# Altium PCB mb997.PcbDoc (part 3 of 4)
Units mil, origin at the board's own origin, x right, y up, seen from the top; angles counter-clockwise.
Board outline 2598.43 x 3818.9 mil, 2 copper layers (Top, Bottom), stack 62.402 mil thick; 205 components, 190 nets, 761 pads, 492 vias.
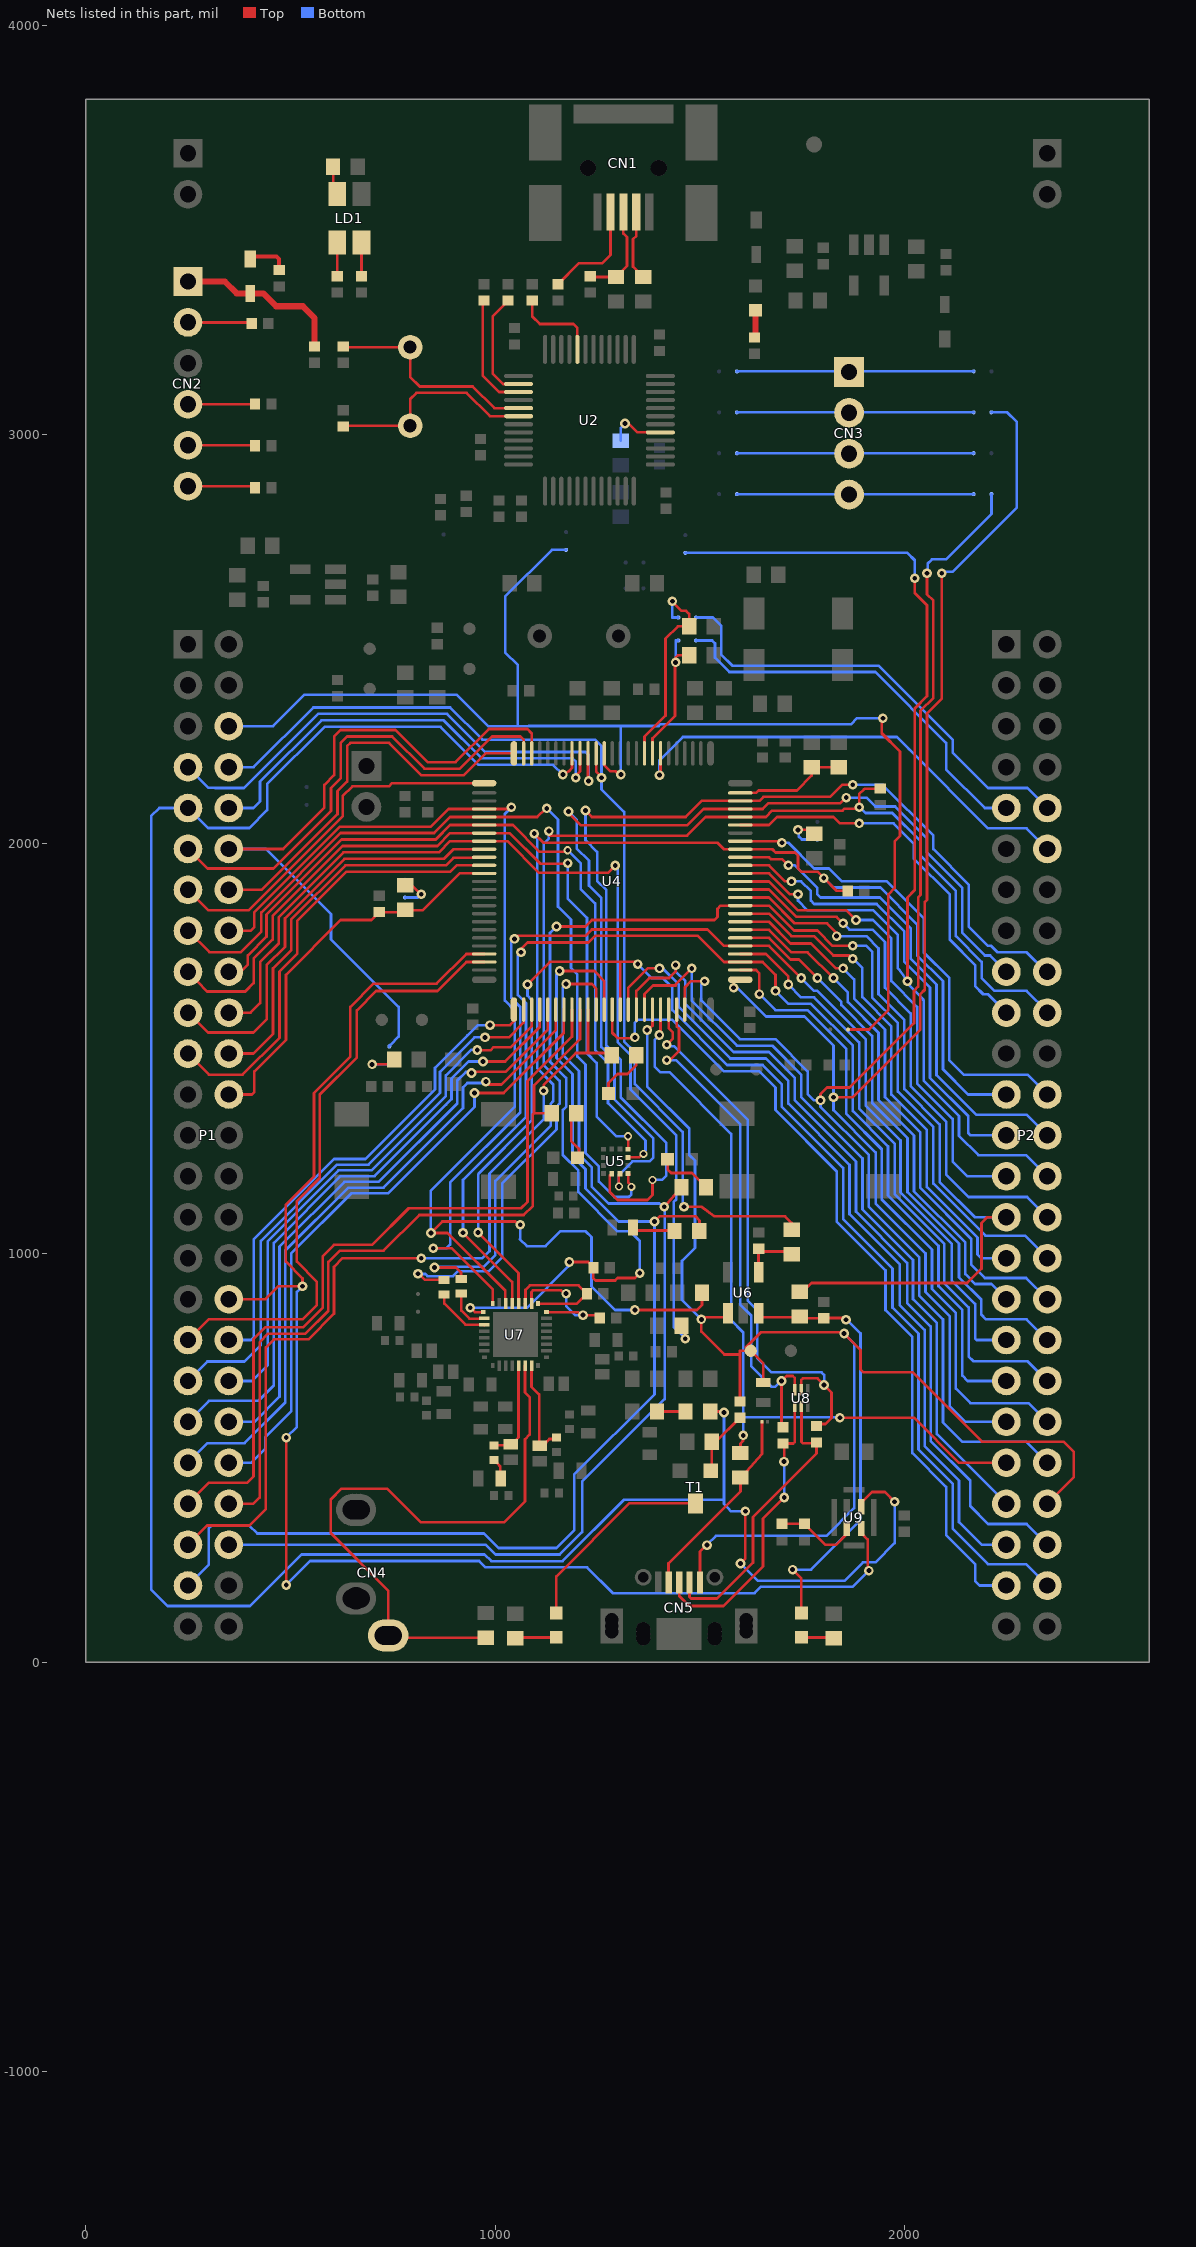
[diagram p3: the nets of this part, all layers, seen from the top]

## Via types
v1: diameter 23.62, hole 11.81, Top to Bottom, 485 vias
v2: diameter 19.68, hole 11.81, Top to Bottom, 7 vias

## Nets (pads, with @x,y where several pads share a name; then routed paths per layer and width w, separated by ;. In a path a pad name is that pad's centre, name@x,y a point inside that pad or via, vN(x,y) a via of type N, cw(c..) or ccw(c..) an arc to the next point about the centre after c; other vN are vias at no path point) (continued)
NetC63_2: C63.2 L6.1 U7.15 | length 254.3
  Top w6.5: U7.15@1088.58,724.59 1088.58,673.06 1107.37,654.27 1107.37,537.14 1105.54,535.31 L6.1@1097.6,535.31 ; L6.1@1110.24,527.6 1115.16,527.6 1124.7,537.14 1124.7,538.11 1132.25,545.66 1145.6,545.66 C63.2@1149.21,549.27
NetC64_1: C64.1 R70.2 | length 51.2
  Top w6.5: C64.1@997.24,493.68 998.23,493.68 1005.02,486.89 1005.02,485.91 1012.32,478.61 1012.32,459.62 R70.2@1019.63,452.3
NetC64_2: C64.2 L7.1 U7.13 | length 243.6
  Top w6.5: C64.2@997.24,529.11 998.23,530.1 1038.03,530.1 1057.09,549.15 U7.13@1057.09,724.59
NetCN1_2: CN1.2 R11.1 | length 171.9
  Top w6.5: CN1.2@1344.73,3543.35 1344.73,3485.44 1336.86,3477.57 1336.86,3410.46 R11.1@1362.17,3385.16
NetCN1_3: CN1.3 R9.1 R10.1 | length 236.6
  Top w6.5: R9.1@1232.24,3386.97 1234.06,3385.16 R10.1@1295.24,3385.16 1295.24,3385.32 1321.94,3412.02 1321.94,3482.43 1313.23,3491.14 CN1.3@1313.23,3543.35
NetCN1_4: CN1.4 R8.1 | length 262.3
  Top w6.5: R8.1@1153.5,3367.28 1205.12,3418.9 1261.73,3418.9 1281.73,3438.9 CN1.4@1281.73,3543.35
NetCN2_1: CN2.1 D2.1 R13.1 | length 415.4
  Top w15: CN2.1@249.21,3374.02 339.2,3374.02 368.33,3344.88 D2.1@401.57,3344.88 433.07,3344.88 464.57,3313.39 529.92,3313.39 558.21,3285.09 R13.1@558.21,3215.5
NetCN2_2: CN2.2 R12.1 | length 157
  Top w6.5: CN2.2@249.21,3274.02 402.83,3274.02 R12.1@405.2,3271.65
NetCN2_4: CN2.4 R15.1 | length 164.2
  Top w6.5: CN2.4@249.21,3074.02 412.28,3074.02 R15.1@413.07,3074.8
NetCN2_5: CN2.5 R16.1 | length 164.5
  Top w6.5: CN2.5@249.21,2974.02 411.5,2974.02 R16.1@413.07,2972.44
NetCN2_6: CN2.6 R17.1 | length 167.8
  Top w6.5: CN2.6@249.21,2874.02 413.07,2874.02 R17.1@413.07,2870.08
NetCN3_1: CN3.1 SB2.1 SB3.2 | length 578.7
  Bottom w6.5: SB2.1@1590.51,3154.37 1862.17,3154.37 SB3.2@2169.25,3154.37
NetCN3_2: CN3.2 SB4.1 SB5.2 | length 578.7
  Bottom w6.5: SB4.1@1590.51,3054.37 1862.17,3054.37 SB5.2@2169.25,3054.37
NetCN3_3: CN3.3 SB6.1 SB7.2 | length 578.7
  Bottom w6.5: SB6.1@1590.51,2954.37 1862.17,2954.37 SB7.2@2169.25,2954.37
NetCN3_4: CN3.4 SB8.1 SB9.2 | length 578.7
  Bottom w6.5: SB8.1@1590.51,2854.37 1862.17,2854.37 SB9.2@2169.25,2854.37
NetCN4_1: CN4.1 R65.1 U7.14 | length 1505.4
  Top w6.5: CN4.1@738.58,65.36 738.58,174.83 598.14,315.27 598.14,398.07 624.25,424.18 736.02,424.18 818.21,342 1021.94,342 1072.71,392.77 1072.71,544.84 1084.24,556.36 1084.24,647.68 1072.71,659.2 U7.14@1072.71,724.47 ; CN4.1@743.78,60.16 R65.1@976.54,60.16
NetCN5_2: CN5.2 R58.2 U8.2 | length 711.6
  Top w6.5: CN5.2@1474.8,194.9 1474.8,159.44 1478.61,155.64 1541.99,155.64 1629.75,243.4 1629.75,354.8 1785.15,510.19 1785.15,529.97 R58.2@1780.32,534.8 ; U8.2@1747.77,624.84 1748.46,624.16 1748.46,538.61 1752.26,534.8 1777.75,534.8 1782.56,534.8 R58.2@1784.91,537.15
NetCN5_3: CN5.3 R60.2 U8.1 | length 733
  Top w6.5: CN5.3@1449.21,194.9 1449.74,194.37 1449.74,162.38 1474.8,137.32 1557.71,137.32 1654.2,233.81 1654.2,350.71 v1(1706.23,402.74) ; R60.2@1703.33,534.49 1705.88,531.93 v1(1705.88,490.3) ; R60.2@1705.88,534.65 1728.21,534.65 1732.02,538.46 U8.1@1732.02,632.74
  Bottom w6.5: v1(1705.88,490.3) 1706.06,490.12 1706.06,402.91 v1(1706.23,402.74)
NetCN5_4: CN5.4 R59.1 U11.1 | length 485.7
  Top w6.5: CN5.4@1423.62,194.9 1423.62,241.67 1599.21,417.26 R59.1@1599.21,451.4 1614.13,465.65 1651.86,509.22 U11.1@1651.86,587.4
NetD2_2: D2.2 R2.1 | length 112.4
  Top w10: D2.2@401.57,3429.13 401.57,3434.9 465.21,3434.9 471.21,3428.9 471.21,3405.51 R2.1@468.82,3405.51 ; R2.1@465.21,3405.51 R2.1@468.82,3405.51 ; R2.1@472.44,3401.89 R2.1@468.82,3405.51
NetLD1_2: LD1.2 R4.2 | length 82.4
  Top w6.5: R4.2@673.19,3386.97 LD1.2@673.19,3469.33
NetLD1_3: LD1.3 R3.2 | length 82.4
  Top w6.5: R3.2@614.13,3386.97 LD1.3@614.13,3469.33
NetLD1_4: LD1.4 R1.1 | length 91.2
  Top w6.5: R1.1@603.82,3654.37 603.82,3587.28 607.09,3590.55 612.15,3595.61 613.82,3583.82 LD1.4@614.13,3583.5
NetLD2_1: LD2.1 R14.1 | length 66.8
  Top w13.78: R14.1@1633.82,3237.36 1636.12,3239.67 LD2.1@1636.12,3303.17
NetLD3_1: LD3.1 R36.1 | length 135.4
  Top w6.5: LD3.1@1276.93,1389.76 1276.93,1415.12 1299.21,1437.41 1322.82,1437.41 1344.95,1459.54 R36.1@1344.95,1483.15
NetLD4_1: LD4.1 R40.1 | length 123.4
  Top w6.5: R40.1@1198.04,1341.61 1185.55,1329.11 1185.55,1273.73 1204.72,1254.55 1204.72,1236.67 LD4.1@1200.95,1232.9
NetLD5_1: LD5.1 R41.1 | length 136.6
  Top w6.5: LD5.1@1421.3,1229.04 1421.3,1204.28 1430.18,1195.4 1480.71,1195.4 R41.1@1515.21,1160.9
NetLD6_1: LD6.1 R42.1 | length 105
  Top w6.5: LD6.1@1336.85,1062.75 1344.39,1055.21 1436.9,1055.21 R42.1@1438.21,1053.9
NetLD7_1: LD7.1 R66.1 | length 100.7
  Top w6.5: R66.1@1049.21,58.9 1050.87,60.55 LD7.1@1149.21,60.55
NetLD7_2: LD7.2 T1.3 | length 503.9
  Top w6.5: LD7.2@1149.21,120.55 1149.21,209.9 1328.21,388.9 1488.21,388.9 T1.3@1489.21,387.9
NetLD8_1: LD8.1 R67.1 | length 80.3
  Top w6.5: LD8.1@1748.03,60.55 1825.98,60.55 R67.1@1827.64,58.9
NetLD8_2: LD8.2 R50.2 R51.2 U6.3 | length 1047.2
  Top w6.5: U6.3@1643.54,842.9 1733.26,842.9 R50.2@1735.98,840.18 ; v1(1726.71,226.4) 1748.03,205.08 LD8.2@1748.03,120.55 ; R50.2@1743.81,845.06 1748.21,840.66 R51.2@1802.76,840.62 ; R51.2@1802.76,840.62 1803.27,841.13 1848.35,841.13 1852.58,836.9 v1(1857.21,836.9)
  Bottom w6.5: v1(1726.71,226.4) 1771.71,226.4 1892.75,347.44 1892.75,803.9 1859.75,836.9 v1(1857.21,836.9)
NetR5_2: R5.2 U2.3 | length 289.2
  Top w6.5: R5.2@972.4,3327.28 972.4,3318.9 969.21,3315.71 969.21,3143.9 1009.21,3103.9 U2.3@1057.11,3103.9
NetR6_2: R6.2 U2.2 | length 267.6
  Top w6.5: R6.2@1031.46,3327.28 1031.46,3326.46 993.9,3288.9 993.9,3148.9 1019.21,3123.58 U2.2@1057.11,3123.58
NetR7_2: R7.2 U2.44 | length 212.5
  Top w6.5: R7.2@1090.51,3327.28 1090.51,3288.9 1109.21,3270.2 1190.81,3270.2 1200.81,3260.2 U2.44@1200.81,3208.23
NetR27_1: R27.1 R28.1 U4.99 | length 278.2
  Top w6.5: U4.99@1598.96,2124.48 1637.62,2124.48 1643.45,2130.31 1737.21,2130.31 1773.21,2166.31 R27.1@1773.21,2186.9 R28.1@1839.21,2186.9
NetR30_1: R30.1 SB18.2 | length 110.5
  Top w6.5: v1(1739.93,2034.05) 1771.41,2034.05 1771.41,2032.57 R30.1@1779.28,2024.7
  Bottom w6.5: v1(1739.93,2034.05) 1741.71,2034.04 1741.71,2017.93 1749.21,2010.43 SB18.2@1787.15,2010.43
NetR32_2: R32.2 SB19.2 | length 91.7
  Top w6.5: R32.2@779.79,1898.78 R32.2@780.5,1899.43 ; R32.2@780.53,1899.46 795.53,1899.46 818.35,1876.65 v1(819.14,1876.65)
  Bottom w6.5: SB19.2@779.79,1868.77 v1@811.27,1868.77 ; v1@811.27,1868.78 v1(819.14,1876.65)
NetR35_1: R35.1 SB20.2 | length 114.6
  Top w6.5: v1(699.21,1460.9) 744.83,1460.9 759.21,1475.28 R35.1@753.21,1472.9
  Bottom w6.5: v1(699.21,1460.9) 740.83,1460.9 SB20.2@741.21,1461.28
NetR45_2: R45.2 R46.1 U6.4 | length 134.5
  Top w6.5: U6.4@1643.54,942.9 R45.2@1643.54,1000.99 ; R45.2@1650.69,1003.76 1717.12,1003.76 R46.1@1724.19,996.69
NetR47_2: R47.2 U7.25 U7.27 | length 328.2
  Top w6.5: U7.27@1072.83,876.13 1073.92,877.22 1073.92,910.15 1084.71,920.95 1203.94,920.95 1213.59,911.3 1214.87,911.3 1224.12,902.05 R47.2@1224.12,900.77 1199.49,876.13 U7.25@1104.33,876.13
NetR53_2: R53.2 U7.24 U7.26 | length 334.6
  Top w6.5: U7.26@1088.58,876.13 1088.58,904.83 1092.39,908.64 1160.92,908.64 1168.79,900.77 v1(1173.29,900.77) ; U7.24@1125,855.47 1202.59,855.47 1209.73,848.32 v1(1214.37,848.32) 1248.45,848.32 R53.2@1255.59,841.18
  Bottom w6.5: v1@1173.43,900.16 1173.43,871.02 1196.61,847.83 1213.87,847.83 v1(1214.37,848.32)
NetR54_2: R54.2 R55.2 | length 70
  Top w6.5: R54.2@1395.2,612.6 R55.2@1465.2,612.6
NetR56_1: R56.1 R57.2 T1.1 | length 165.3
  Top w6.5: T1.1@1526.71,467.9 1529.21,470.4 R57.2@1529.21,538.9 1539.72,538.9 R56.1@1598.27,597.45
NetR61_1: R61.1 U7.3 | length 141.6
  Top w6.5: R61.1@875.58,898.43 875.58,876.38 926.87,825.08 972.34,825.08 U7.3@973.42,824
NetR62_1: R62.1 U7.2 | length 106.1
  Top w6.5: R62.1@917.33,901.18 917.33,859.31 936.89,839.75 U7.2@973.42,839.75
NetR63_2: R63.2 R64.1 U9.2 | length 227.6
  Top w6.5: R63.2@1700.58,338.39 1732.06,338.39 ; 1732.06,338.5 1732.06,338.39 ; 1732.08,338.52 R64.1@1755.67,338.62 ; U9.2@1859,326.76 1859,313.68 1832.23,286.92 1807.14,286.92 R64.1@1755.67,338.39 1732.06,338.39
NetR68_1: R68.1 U2.29 | length 141.7
  Top w6.5: v1(1317.21,3026.9) 1325.79,3026.9 1347.21,3005.47 U2.29@1403.57,3005.47
  Bottom w6.5: R68.1@1307.08,2984.84 1307.08,3014.65 1306.83,3014.9 1306.83,3016.52 v1(1317.21,3026.9)
NRST: P1.6 SB1.1 SB11.2 U4.14 | length 3264.6
  Top w6.5: U4.14@1266.28,2220.94 1266.28,2192.91 1282.03,2177.17 1294.43,2177.17 1300.52,2171.08 v1(1307.09,2169.29) ; SB1.1@1861.93,1546.11 1913.07,1546.11 1913.24,1545.94 1960.63,1593.33 1960.63,1876.65 1976.03,1892.05 1976.03,2005.72 1989.21,2018.9 1989.21,2225.49 1944.55,2270.15 1944.55,2301.66 v1@1952.42,2301.66 ; v1(1947.21,2306.9) v1@1952.42,2301.69
  Bottom w6.5: P1.6@349.21,2287.4 457.12,2287.4 534.31,2364.59 905.71,2364.59 982.9,2287.4 1055.24,2287.4 ; SB11.2@1173.21,2718.28 1138.21,2718.28 1024.49,2604.56 1024.49,2467.76 1055.24,2437.01 1055.24,2287.4 ; v1(1307.09,2169.29) 1307.09,2287.88 ; v1(1947.21,2306.9) 1884.21,2306.9 1869.21,2291.9 1403.23,2291.9 1399.21,2287.88 1307.09,2287.88 ; 1055.24,2287.4 1082.19,2287.88 1307.09,2287.88
OSC_IN: C6.2 U2.5 X1.2 | length 554.9
  Top w6.5: C6.2@628.41,3215.5 C6.2@627.24,3213.56 ; U2.5@1057.11,3064.53 997.82,3064.53 944.85,3117.5 815.61,3117.5 792.21,3140.9 X1.2@792.21,3213.56 C6.2@627.24,3213.56 ; C6.2@627.24,3213.56 623.23,3206.9 623.23,3213.56 C6.2@627.24,3213.56
OSC_OUT: C9.2 U2.6 X1.1 | length 524.5
  Top w6.5: C9.2@628.41,3019.5 630.35,3021.43 X1.1@792.21,3021.43 792.21,3086.3 807.81,3101.9 930.16,3101.9 987.21,3044.84 U2.6@1057.11,3044.84
PA0: P1.12 SB20.1 U4.23 | length 1785.3
  Top w6.5: P1.12@349.21,1987.4 481.72,1987.4 582.47,2088.15 582.47,2144.23 606.37,2168.12 606.37,2262.56 621.82,2278.02 756.18,2278.02 834.88,2199.32 903.32,2199.32 984.41,2280.41 1078.85,2280.41 1089.11,2270.15 U4.23@1089.11,2220.94
  Bottom w6.5: P1.12@349.21,1987.4 439.78,1987.4 598.78,1828.4 598.78,1766.47 764.05,1601.2 764.05,1528.58 744.11,1508.64 741.21,1505.74 SB20.1@741.21,1504.58
PA1: P1.11 U4.24 | length 1159
  Top w6.5: P1.11@249.21,1987.4 297.01,1939.61 457.92,1939.61 598.78,2080.47 598.78,2136.36 622.39,2159.97 622.39,2246.54 638.13,2262.28 748.31,2262.28 827.01,2183.58 913.58,2183.58 992.28,2262.28 1061.56,2262.28 1069.43,2254.41 U4.24@1069.43,2220.94
PA2: P1.14 U4.25 | length 983.4
  Top w6.5: P1.14@349.21,1887.4 429.38,1887.4 614.52,2072.54 614.52,2128.49 638.13,2152.1 638.13,2238.67 646,2246.54 740.44,2246.54 819.14,2167.84 923.44,2167.84 976.54,2220.94 U4.25@1045.81,2220.94
PA3: P1.13 U4.26 | length 902.2
  Top w6.5: P1.13@249.21,1887.4 299.32,1837.3 397.61,1837.3 627.21,2066.9 627.21,2116.24 651.21,2140.24 740.44,2140.24 748.31,2148.11 U4.26@972.97,2148.11
PA4: P1.16 R48.2 U4.29 U7.30 | length 3171.6
  Top w6.5: P1.16@349.21,1787.4 402.03,1787.4 411.37,1796.74 411.37,1833.06 620.23,2041.92 842.75,2041.92 885.95,2085.11 U4.29@972.97,2085.11 1038.15,2085.11 1039.5,2086.47 v1(1039.5,2089.14) ; U7.30@1025.59,876.17 1025.59,880.5 1024.51,881.58 1024.51,907.89 883.5,1048.9 v1(842.99,1048.9) 870.99,1076.9 1048.84,1076.9 1056.84,1068.9 v1(1061.21,1068.9) ; v1(1341.21,860.9) 1493.2,860.9 1505.2,872.9 R48.2@1505.2,902.6
  Bottom w6.5: v1(842.99,1048.9) 842.75,1049.14 842.75,1152.49 1047.62,1357.36 1047.62,1592.9 1023.62,1616.9 1023.62,2073.4 1039.36,2089.14 v1(1039.5,2089.14) ; v1(1061.21,1068.9) 1061.21,1033.9 1060.71,1033.4 1077.21,1016.9 1122.74,1016.9 1158.74,1052.9 1221.21,1052.9 1235.41,1038.7 1235.41,918.7 1293.21,860.9 v1(1341.21,860.9)
PA5: P1.15 U4.30 U5.1 | length 2192.1
  Top w6.5: P1.15@249.21,1787.4 301.32,1735.29 378.42,1735.29 428.62,1785.49 428.62,1832.3 622.49,2026.18 850.72,2026.18 889.97,2065.43 1102.36,2065.43 1123.55,2086.61 v1(1125.98,2086.61) ; U5.1@1324.72,1194.37 U5.1@1325.22,1194.37 ; U5.1@1327.87,1191.71 U5.1@1325.22,1194.37 ; v2(1332.52,1161.77) 1332.52,1164.86 1325.22,1172.17 U5.1@1325.22,1194.37
  Bottom w6.5: v1(1125.98,2086.61) 1153.54,2059.06 1153.54,1846.46 1185.04,1814.96 1185.04,1696.85 1200.79,1681.1 1200.79,1480.32 1220.47,1460.63 1220.47,1244.49 1253.37,1211.6 1253.37,1174.43 1290.93,1136.87 1326.32,1136.87 1332.52,1143.06 v2(1332.52,1161.77)
PA6: P1.18 U4.31 U5.3 | length 1918.6
  Top w6.5: P1.18@349.21,1687.4 378.42,1687.4 395.48,1704.46 395.48,1727.12 441.24,1772.87 441.24,1826.92 624.75,2010.44 854.67,2010.44 889.97,2045.74 U4.31@972.97,2045.74 1043.31,2045.74 1108.74,1980.32 1177.17,1980.32 v2(1177.17,1984.25) ; U5.3@1324.72,1233.74 1351.76,1233.74 v2@1362.27,1244.25 ; v2@1360.6,1242.47 v2(1362.27,1242.47)
  Bottom w6.5: v2(1177.17,1984.25) 1208.66,1952.76 1208.66,1889.76 1244.09,1854.33 1244.09,1496.06 1275.59,1464.57 1275.59,1366.14 1367.32,1274.41 1367.32,1251.08 1362.27,1246.03 v2(1362.27,1242.47)
PA7: P1.17 U4.32 U5.4 | length 1986.8
  Top w6.5: P1.17@249.21,1687.4 296.07,1638.9 389.21,1638.9 409.9,1659.59 409.9,1719.25 456.21,1765.56 456.21,1823.9 627.01,1994.7 858.61,1994.7 889.97,2026.06 1035.43,2026.06 1110.24,1951.26 1173.23,1951.26 1174.73,1952.76 v1(1177.17,1952.76) ; U5.4@1324.85,1253.56 v2(1324.85,1285.3)
  Bottom w6.5: v1(1177.17,1952.76) 1177.17,1866.14 1224.41,1818.9 1224.41,1488.19 1248.03,1464.57 1248.03,1333.46 1296.2,1285.3 v2(1324.85,1285.3)
PA8: P2.43 U4.67 | length 1858.3
  Top w6.5: U4.67@1364.7,1594.96 1364.7,1632.68 1385.78,1653.76 1440.87,1653.76 1440.87,1656.29 v1(1480.22,1695.64)
  Bottom w6.5: v1(1480.22,1695.64) 1480.22,1616.94 1590.4,1506.76 1676.97,1506.76 1747.8,1435.93 1747.8,1380.84 1897.33,1231.31 1897.33,1106.9 2020.88,983.35 2020.88,887.4 2079.21,829.07 2079.21,557.4 P2.43@2249.21,387.4
PA9: C49.1 CN5.1 P2.44 R56.2 U4.68 U6.1 U10.1 | length 3351.8
  Top w6.5: v1(1371.21,1544.9) 1373.72,1544.9 1384.39,1555.57 U4.68@1384.39,1594.96 ; CN5.1@1500.39,194.9 1500.39,270.5 1515.99,286.1 v1(1517.61,286.1) ; U6.1@1568.74,842.9 1511.63,842.9 1507.05,838.31 v1(1503.83,837.81) 1503.83,808.09 1559.97,751.96 1598.27,751.96 ; R56.2@1598.27,637.45 1598.27,751.96 ; 1612.23,769.7 1648.86,806.33 1849.55,806.33 v1(1852.64,803.24) 1892.75,763.13 1892.75,715.36 1899.21,708.9 2019.21,708.9 2189.21,538.9 2389.21,538.9 2413.99,514.12 2413.99,452.18 P2.44@2349.21,387.4 ; C49.1@1623.4,761.32 1598.27,761.32 1598.27,751.96 ; C49.1@1624.5,760.98 1654.68,730.8 U10.1@1654.68,683.5
  Bottom w6.5: v1(1371.21,1544.9) 1371.21,1407.04 1474.13,1304.12 1474.13,1239.82 1488.09,1225.85 1488.09,1012.38 1456.61,980.9 1456.61,885.03 v1(1503.83,837.81) ; v1(1517.61,286.1) 1517.61,287.61 1539.06,309.05 1809.37,309.05 1877.27,376.96 1877.27,778.61 v1(1852.64,803.24)
PA10: P2.41 R59.2 U4.69 | length 1884.3
  Top w6.5: v1(1401.21,1532.9) 1404.07,1535.76 U4.69@1404.07,1594.96 ; R59.2@1599.21,511.4 1599.21,534.47 1606.14,541.4 v1(1606.14,554.49) ; v1(1842.24,597.64) 2023.19,597.64 2133.43,487.4 P2.41@2249.21,487.4
  Bottom w6.5: v1(1401.21,1532.9) 1401.21,1532.52 1389.59,1520.9 1389.59,1456.02 1404.21,1441.4 1426.71,1441.4 1576.71,1291.4 1576.71,835.76 1606.14,806.33 1606.14,598.33 ; v1(1606.14,554.49) 1606.14,598.33 ; v1(1842.24,597.64) 1841.55,598.33 1606.14,598.33
PA11: R58.1 U4.70 U8.5 | length 1377.5
  Top w6.5: v1(1419.21,1508.9) 1434.21,1523.9 1434.21,1538.9 1423.76,1549.35 U4.70@1423.76,1594.96 ; U8.5@1747.77,674.08 1747.77,689.78 1751.58,693.59 1787.39,693.59 v1(1803.63,677.35) 1821.87,659.11 1821.87,597 1807.23,582.36 R58.1@1785.15,582.36
  Bottom w6.5: v1(1419.21,1508.9) 1422.49,1505.62 1436.55,1505.62 1617.15,1325.02 1617.15,883.22 1640.19,860.18 1640.19,743.92 1675.63,708.48 1797.34,708.48 1803.63,702.19 v1(1803.63,677.35)
PA12: R60.1 U4.71 U8.6 | length 1275
  Top w6.5: v1(1419.21,1471.4) 1426.71,1471.4 1449.21,1493.9 1449.21,1548.13 1443.44,1553.9 U4.71@1443.44,1594.96 ; R60.1@1703.33,574.49 1699.77,578.05 1699.77,680.27 1703.33,683.83 v1(1699.77,687.39) 1700.18,687.39 1712.14,699.35 1726.71,699.35 1732.02,694.04 U8.6@1732.02,666.18
  Bottom w6.5: v1(1419.21,1471.4) 1441.71,1471.4 1599.01,1314.1 1599.01,873.43 1625.76,846.69 1625.76,723.11 1675.77,673.1 1683.57,673.1 1697.86,687.39 v1(1699.77,687.39)
PA13: P2.42 SB9.1 U4.72 | length 3510.6
  Top w6.5: U4.72@1463.13,1594.96 1463.13,1648.42 1478.87,1664.16 v1(1511.7,1664.16) ; v1(1795.02,1372.97) 1795.02,1388.71 1810.76,1404.45 1865.85,1404.45 2023.25,1561.85 2023.25,1640.55 2033.41,1650.7 2033.41,1868.9 2039.41,1874.9 2039.41,2325.49 2070.47,2356.55 2070.47,2594.47 2055.21,2609.73 v1(2055.21,2660.9)
  Bottom w6.5: v1(1511.7,1664.16) 1503.83,1656.29 1503.83,1616.94 1598.27,1522.5 1684.84,1522.5 1763.54,1443.8 1763.54,1388.71 1779.28,1372.97 v1(1795.02,1372.97) 1795.02,1357.23 1913.07,1239.18 1913.07,1112.9 2036.1,989.87 2036.1,895.79 2094.08,837.81 2094.08,585.97 2141.3,538.75 2297.87,538.75 P2.42@2349.21,487.4 ; v1(2055.21,2660.9) 2056.98,2660.9 2056.98,2684.9 2067.21,2695.13 2101.29,2695.13 2212.56,2806.4 SB9.1@2212.56,2854.37
PA14: P2.39 SB5.1 U4.76 | length 3439.7
  Top w6.5: v1(1582.53,1648.42) 1582.53,1664.16 1598.96,1664.16 U4.76@1598.96,1667.79 ; v1(1826.5,1380.84) 1873.72,1380.84 2038.99,1546.11 2038.99,1632.68 2049.65,1643.33 2049.65,1857.33 2055.21,1862.9 2055.21,2318.9 2091.21,2354.9 v1(2091.21,2660.9)
  Bottom w6.5: v1(1582.53,1648.42) 1591.24,1648.42 1661.65,1578.01 1755.25,1578.01 1826.5,1506.76 v1(1826.5,1380.84) 1826.5,1349.11 1929.53,1246.08 1929.53,1120.95 2051.27,999.21 2051.27,904.95 2110.54,845.68 2110.54,626.03 2149.17,587.4 P2.39@2249.21,587.4 ; v1(2091.21,2660.9) 2094.84,2664.53 2117.69,2664.53 2274.21,2821.05 2274.21,3031.4 2251.24,3054.37 SB5.1@2212.56,3054.37
PA15: P2.40 U4.77 | length 1566.8
  Top w6.5: U4.77@1598.96,1691.41 1637.62,1691.41 1645.49,1683.54 v1(1645.49,1632.68)
  Bottom w6.5: v1(1645.49,1632.68) 1684.84,1593.33 1763.54,1593.33 1857.98,1498.89 1857.98,1340.13 1944.55,1253.56 1944.55,1130.9 2067.21,1008.24 2067.21,911.9 2125.56,853.55 2125.56,668.9 2161.27,633.19 2303.43,633.19 P2.40@2349.21,587.4
PB0: P1.22 U4.35 | length 960.3
  Top w6.5: P1.22@349.21,1487.4 409.12,1487.4 457.12,1535.4 457.12,1695.64 501.21,1739.73 501.21,1814.9 633.79,1947.48 879.53,1947.48 897.84,1965.79 951.71,1965.79 952.93,1967 U4.35@972.97,1967
PB1: P1.21 U4.36 | length 1099
  Top w6.5: P1.21@249.21,1487.4 300.69,1435.93 382.86,1435.93 472.86,1525.93 472.86,1687.77 516.21,1731.12 516.21,1811.9 635.81,1931.5 889.89,1931.5 905.71,1947.32 U4.36@972.97,1947.32
PB2: P1.24 R32.1 R34.2 U4.37 | length 974
  Top w6.5: P1.24@349.21,1387.4 405.21,1387.4 411.21,1393.4 411.21,1443.51 488.6,1520.9 488.6,1679.9 622.39,1813.69 697.48,1813.69 R34.2@716.83,1833.04 779.79,1833.04 R32.1@779.79,1837.3 ; R32.1@779.79,1838.78 R32.1@779.79,1837.3 ; U4.37@972.97,1927.63 913.02,1927.63 822.68,1837.3 R32.1@779.79,1837.3
PB3: P2.28 SB12.2 U4.89 | length 2893.3
  Top w6.5: U4.89@1598.96,1927.63 1669.1,1927.63 1720.09,1876.65 v1(1739.93,1876.65) ; v1(2007.51,1664.16) 2007.51,1868.9 2025.21,1886.6 2025.21,2330.9 2055.21,2360.9 2055.21,2582.9 2025.21,2612.9 v1(2025.21,2648.9)
  Bottom w6.5: SB12.2@1464.48,2710.86 2007.21,2710.87 2025.21,2692.87 v1(2025.21,2648.9) ; v1(1739.93,1876.65) 1739.93,1860.91 1763.54,1837.3 1923.9,1837.3 1983.9,1777.3 1983.9,1695.64 1987.84,1691.7 v1(2007.51,1664.16) 2007.51,1658.28 2045.28,1620.51 2045.28,1618.52 2046.86,1616.94 2046.86,1421.25 2133.43,1334.68 2133.43,1286.4 2180.65,1239.18 2297.44,1239.18 P2.28@2349.21,1187.4
PB4: P2.25 U4.90 | length 1134.4
  Top w6.5: U4.90@1598.96,1947.32 1669.1,1947.32 1708.37,1908.05 1708.45,1908.13 v1(1724.19,1908.13)
  Bottom w6.5: v1(1724.19,1908.13) 1747.8,1908.13 1771.41,1884.52 1771.41,1860.91 1779.28,1853.04 1932.14,1853.04 1999.64,1785.54 1999.64,1711.38 2062.6,1648.42 2062.6,1428.01 2155.92,1334.69 2155.92,1293.19 2161.71,1287.4 P2.25@2249.21,1287.4
PB5: P2.26 U4.91 | length 1214.4
  Top w6.5: U4.91@1598.96,1967 1669.1,1967 1673.56,1962.54 1701.26,1962.54 v1(1716.32,1947.48)
  Bottom w6.5: v1(1716.32,1947.48) 1732.06,1947.48 1787.15,1892.39 1787.15,1876.65 1795.02,1868.78 1940.38,1868.78 2015.38,1793.78 2015.38,1719.25 2078.34,1656.29 2078.34,1434.77 2175.2,1337.91 2298.7,1337.91 P2.26@2349.21,1287.4
PB6: P2.23 R33.2 R62.2 U4.92 | length 3033.1
  Top w6.5: v1(851.74,964.62) 904.22,964.62 916.25,952.6 916.25,937.7 R62.2@917.33,936.61 ; v1(1095.21,2024.9) 1117.54,2002.57 1543,2002.57 1558.88,1986.69 U4.92@1598.96,1986.69 1676.97,1986.69 1684.77,1978.89 1732.06,1978.89 1739.9,1971.05 1739.9,1939.64 1747.8,1931.74 1787.15,1931.74 v1(1802.89,1916) 1833.63,1885.26 1850.85,1885.26 R33.2@1861.59,1884.52
  Bottom w6.5: v1(851.74,964.62) 853.41,966.29 971.24,966.29 1000.37,995.43 1000.37,1176.28 1135.83,1311.74 1135.83,1365.1 1141.81,1371.08 1141.81,1412.32 1102.46,1451.67 1102.46,2012.9 1095.21,2020.15 v1(1095.21,2024.9) ; v1(1802.89,1916) 1803.55,1916 1826.5,1893.04 1941.12,1893.04 2031.12,1803.04 2031.12,1727.12 2094.08,1664.16 2094.08,1449.03 2155.71,1387.4 P2.23@2249.21,1387.4
PB7: P2.24 U4.93 | length 1173.2
  Top w6.5: U4.93@1598.96,2006.37 1690.74,2006.37 1694.54,2002.57 v1(1700.58,2002.57)
  Bottom w6.5: v1(1700.58,2002.57) 1716.32,2002.57 1779.28,1939.61 1815.52,1939.61 1847,1908.13 1956.86,1908.13 2046.86,1818.13 2046.86,1734.99 2109.82,1672.03 2109.82,1470.79 2144.68,1435.93 2300.69,1435.93 P2.24@2349.21,1387.4
PB8: P2.19 U4.95 | length 972.6
  Top w6.5: U4.95@1598.96,2045.74 1669.1,2045.74 1688.89,2065.53 1826.5,2065.53 1842.24,2049.79 v1(1889.46,2049.79)
  Bottom w6.5: v1(1889.46,2049.79) 1973.32,2049.79 2023.25,1999.86 2023.25,1963.22 2110.79,1875.68 2110.79,1765.5 2172.78,1703.51 2172.78,1652.15 2192.58,1632.35 2204.26,1632.35 P2.19@2249.21,1587.4
PB9: P2.20 R29.2 R61.2 U4.96 | length 3093.6
  Top w6.5: v1(811.27,949.45) 813.89,949.45 828.84,934.5 R61.2@870.44,934.5 ; R61.2@864.29,940.65 R61.2@870.44,934.5 ; R61.2@872.84,934.5 871.64,934.5 R61.2@870.44,934.5 ; v1(1131.21,2030.9) 1127.47,2030.9 1128.41,2029.28 1133.94,2019.71 1468.68,2019.71 1514.4,2065.43 1661.23,2065.43 1676.85,2081.05 1849,2081.05 1853.87,2085.92 1878.37,2085.92 1881.59,2089.14 v1(1889.46,2089.14) 1889.46,2121.29 1901.21,2133.04 1903.07,2134.9 R29.2@1941.21,2134.9
  Bottom w6.5: v1(811.27,949.45) 811.86,948.86 829.32,948.86 834.63,943.55 897.04,943.55 909.35,955.86 975.56,955.86 984.41,955.86 1017.09,988.53 1017.09,1169.43 1149.68,1302.02 1149.68,1357.23 1157.55,1365.1 1157.55,1420.19 1118.2,1459.54 1118.2,1999.89 1131.21,2012.9 v1(1131.21,2030.9) ; v1(1889.46,2089.14) 1891.49,2089.14 1905.2,2075.42 1970.19,2075.42 2038.99,2006.62 2038.99,1971.09 2125.56,1884.52 2125.56,1774.34 2188.52,1711.38 2188.52,1672.03 2220,1640.55 2298.7,1640.55 2349.21,1590.04 P2.20@2349.21,1587.4
PB10: P1.34 U4.47 U9.3 | length 3693.9
  Top w6.5: P1.34@349.21,887.4 439.21,887.4 470.71,918.9 v1(529.21,918.9) 529.21,938.05 488.37,978.9 488.37,1118.05 557.21,1186.9 557.21,1390.9 646,1479.69 646,1601.2 702.93,1658.12 856.66,1658.12 929.32,1730.78 U4.47@972.97,1730.78 ; v1(489.21,188.9) v1(489.21,548.9) ; U9.3@1890.31,330.89 U9.3@1894.43,326.76 ; U9.3@1894.43,315.94 1910.28,300.09 1910.28,226.74 v1(1913.07,223.95)
  Bottom w6.5: v1(489.21,188.9) 547.87,247.56 960.8,247.56 976.54,231.82 1224.21,231.82 1287.21,168.82 1633.51,168.82 1649.29,184.6 1873.72,184.6 v1(1913.07,223.95) ; v1(489.21,548.9) 515.21,574.9 515.21,904.9 v1(529.21,918.9)
PB11: P1.35 U4.48 | length 1511.5
  Top w6.5: P1.35@249.21,787.4 299.67,837.86 529.21,837.86 564.21,872.86 564.21,928.9 515.21,978.9 515.21,1126.9 571.21,1182.9 571.21,1386.9 661.74,1477.43 661.74,1593.19 708.96,1640.41 858.63,1640.41 929.32,1711.1 U4.48@972.97,1711.1
PB12: P1.36 U4.51 | length 1219.1
  Top w6.5: v1(987.21,1556.9) 1036.22,1556.9 1045.81,1566.48 U4.51@1045.81,1594.96
  Bottom w6.5: P1.36@349.21,787.4 403.21,787.4 410.21,794.4 410.21,1033.9 606.21,1229.9 683.21,1229.9 852.71,1399.4 852.71,1452.4 931.76,1531.44 932.29,1531.44 957.75,1556.9 v1(987.21,1556.9)
PB13: P1.37 U4.52 | length 1394.8
  Top w6.5: v1(975.21,1526.9) 1033.43,1526.9 1069.43,1562.9 U4.52@1069.43,1594.96
  Bottom w6.5: P1.37@249.21,687.4 296.71,734.9 387.21,734.9 427.21,774.9 427.21,1029.9 613.21,1215.9 690.21,1215.9 865.21,1390.9 865.21,1442.9 949.21,1526.9 v1(975.21,1526.9)
PB14: P1.38 U4.53 | length 1347.1
  Top w6.5: v1(956.21,1495.9) 989.24,1495.9 996.24,1502.9 1038.03,1502.9 1089.11,1553.98 U4.53@1089.11,1594.96
  Bottom w6.5: P1.38@349.21,687.4 405.21,687.4 444.46,726.65 444.46,1029.15 617.21,1201.9 697.21,1201.9 879.21,1383.9 879.21,1433.9 942.21,1496.9 955.21,1496.9 v1(956.21,1495.9)
PB15: P1.39 U4.54 | length 1535
  Top w6.5: v1(970.21,1467.9) 1024.25,1467.9 1108.8,1552.44 U4.54@1108.8,1594.96
  Bottom w6.5: P1.39@249.21,587.4 300.42,638.61 420.93,638.61 459.21,676.9 459.21,1024.96 622.15,1187.9 705.15,1187.9 879.68,1362.43 893.21,1375.96 893.21,1425.9 935.21,1467.9 v1(970.21,1467.9)
PC0: P1.8 R46.2 U4.15 | length 2579.9
  Top w6.5: U4.15@1246.59,2220.94 1246.59,2177.17 1259.84,2163.92 v1(1259.84,2161.42) ; v1(1461.21,1112.9) 1503.83,1112.9 1535.31,1089.65 1708.45,1089.65 1724.19,1073.91 R46.2@1724.19,1056.69
  Bottom w6.5: P1.8@349.21,2187.4 409.9,2187.4 555.61,2333.11 889.97,2333.11 968.69,2254.39 1244.12,2254.39 1259.84,2238.67 v1(1259.84,2161.42) 1259.84,2132.9 1314.95,2077.79 1314.95,1517.16 1341.21,1490.9 1341.21,1412.9 1458.2,1295.91 1458.2,1118.9 1462.7,1114.39 v1(1461.21,1112.9)
PC1: P1.7 U4.16 | length 1248
  Top w6.5: U4.16@1226.91,2220.94 1226.91,2154.98 v1(1228.35,2153.54)
  Bottom w6.5: P1.7@249.21,2187.4 299.72,2136.89 314.93,2136.89 315.46,2136.36 386.29,2136.36 567.3,2317.37 882.1,2317.37 975.06,2224.41 1220.47,2224.41 1228.35,2216.54 v1(1228.35,2153.54)
PC2: P1.10 U4.17 | length 1109.7
  Top w6.5: v1(1196.85,2161.42) 1196.85,2166.79 1207.22,2177.17 U4.17@1207.22,2220.94
  Bottom w6.5: P1.10@349.21,2087.4 409.45,2087.4 425.2,2103.15 425.2,2151.65 575.17,2301.63 874.23,2301.63 967.2,2208.66 1188.98,2208.66 1196.85,2200.79 v1(1196.85,2161.42)
PC3: P1.9 R55.1 U4.18 U9.4 | length 5802.3
  Top w6.5: v1(1165.35,2169.29) 1179.67,2177.17 1187.54,2185.04 U4.18@1187.54,2220.94 ; R55.1@1525.2,612.6 1556.69,612.6 v1(1559.06,610.24) ; v1(1599.21,241.4) 1611.22,253.41 v1(1611.22,368.9) ; U9.4@1892.75,387.9 1920.69,415.84 1952.37,415.84 v1(1976.03,392.17)
  Bottom w6.5: v1(1165.35,2169.29) 1141.73,2192.91 959.34,2192.91 866.36,2285.89 583.04,2285.89 442.82,2145.67 442.82,2082.23 399.22,2038.63 297.98,2038.63 P1.9@249.21,2087.4 179.21,2087.4 159.21,2067.4 159.21,177.38 199.21,137.38 400.98,137.38 526.9,263.3 973.98,263.3 990.36,246.92 1164.78,246.92 1315.3,397.43 1559.06,397.43 ; v1(1559.06,610.24) 1559.06,397.43 ; v1(1599.21,241.4) 1641.71,198.9 1853.43,198.9 1898.65,244.13 1928.91,244.13 1976.03,291.25 v1(1976.03,392.17) ; v1(1611.22,368.9) 1576.71,368.9 1569.21,376.4 1559.06,386.56 1559.06,397.43
PC4: P1.20 R49.1 U4.33 | length 2525.4
  Top w6.5: P1.20@349.21,1587.4 402.03,1587.4 425.64,1611.01 425.64,1711.38 471.21,1756.95 471.21,1820.9 629.27,1978.96 862.56,1978.96 889.97,2006.37 U4.33@972.97,2006.37 1029.48,2006.37 1106.96,1928.9 1275.21,1928.9 v1(1293.21,1946.9) ; R49.1@1455.13,822.07 1464.48,820.59 v1(1464.48,790.59)
  Bottom w6.5: v1(1293.21,1946.9) 1299.21,1940.9 1299.21,1515.75 1330.71,1484.25 1330.71,1399.4 1442.67,1287.44 1442.67,1131.36 1436.21,1124.9 1436.21,818.86 v1(1464.48,790.59)
PC5: P1.19 U4.34 | length 1047.5
  Top w6.5: P1.19@249.21,1587.4 298.38,1538.9 409.21,1538.9 441.38,1571.07 441.38,1703.51 486.21,1748.34 486.21,1817.9 631.53,1963.22 874.23,1963.22 897.7,1986.69 U4.34@972.97,1986.69
PC6: P2.47 U4.63 | length 2058.2
  Top w6.5: U4.63@1285.96,1594.96 1285.96,1538.24 1299.21,1524.99 1339.3,1524.99 v1(1341.21,1526.9)
  Bottom w6.5: v1(1341.21,1526.9) 1341.21,1562.9 1348.03,1569.72 1433,1569.72 1558.92,1443.8 1645.49,1443.8 1684.84,1404.45 1684.84,1349.36 1834.37,1199.83 1834.37,1076.9 1953.66,957.61 1953.66,860.18 2019.21,794.63 2019.21,511.31 2101.95,428.57 2101.95,310.52 2172.78,239.69 2172.78,198.61 2183.99,187.4 P2.47@2249.21,187.4
PC7: P2.48 U4.64 U7.28 | length 3344.7
  Top w6.5: v1(958.2,1050.24) 1057.09,951.35 U7.28@1057.09,876.13 ; v1(1078.85,1656.29) 1133.94,1711.38 1305.65,1711.38 ; U4.64@1305.65,1594.96 1305.65,1711.38 ; v1(1348.21,1705.9) 1342.73,1711.38 1305.65,1711.38
  Bottom w6.5: v1(958.2,1050.24) 958.2,1192.29 960.8,1194.9 1089.21,1323.31 1089.21,1618.54 1078.85,1628.9 v1(1078.85,1656.29) ; v1(1348.21,1705.9) 1382.08,1672.03 1409.39,1672.03 1433,1648.42 1433,1593.33 1566.79,1459.54 1653.36,1459.54 1700.58,1412.32 1700.58,1357.23 1850.11,1207.7 1850.11,1082.9 1970.88,962.13 1970.88,866.57 2034.21,803.24 2034.21,519.92 2117.69,436.44 2117.69,326.26 2204.26,239.69 2296.93,239.69 P2.48@2349.21,187.4
PC8: P2.45 U4.65 | length 1999.4
  Top w6.5: U4.65@1325.33,1594.96 1325.33,1648.42 1372.55,1695.64 v1(1401.52,1695.64)
  Bottom w6.5: v1(1401.52,1695.64) 1409.39,1695.64 1448.74,1656.29 1448.74,1601.2 1574.66,1475.28 1661.23,1475.28 1716.32,1420.19 1716.32,1365.1 1865.85,1215.57 1865.85,1094.9 1988.13,972.62 1988.13,872.93 2049.21,811.85 2049.21,528.53 2133.43,444.31 2133.43,342.49 2188.52,287.4 P2.45@2249.21,287.4
PC9: P2.46 U4.66 | length 2075.1
  Top w6.5: U4.66@1345.02,1594.96 1345.02,1640.55 1376.5,1672.03 1425.13,1672.03 1440.87,1687.77 v1(1440.87,1703.51)
  Bottom w6.5: v1(1440.87,1703.51) 1440.87,1687.77 1464.48,1664.16 1464.48,1609.07 1582.53,1491.02 1669.1,1491.02 1732.06,1428.06 1732.06,1372.97 1881.59,1223.44 1881.59,1100.9 2006.49,976 2006.49,878.18 2064.21,820.46 2064.21,540.92 2160.83,444.31 2160.83,381.35 2204.26,337.91 2298.7,337.91 P2.46@2349.21,287.4
PC10: P2.37 U4.78 U7.29 | length 2980.2
  Top w6.5: v1(921.25,1049.42) 1041.34,929.34 1041.34,914.67 U7.29@1041.34,876.13 ; v1(1063.11,1734.99) 1063.11,1742.86 1078.85,1758.6 1227.83,1758.6 1244.12,1774.89 1495.13,1774.89 1558.92,1711.1 U4.78@1598.96,1711.1 1653.36,1711.1 1684.84,1679.62 v1(1684.84,1640.55)
  Bottom w6.5: v1(921.25,1049.42) 921.25,1178.7 921.45,1178.9 1075.21,1332.66 1075.21,1610.56 1055.12,1630.65 1055.12,1726.99 v1(1063.11,1734.99) ; v1(1684.84,1640.55) 1716.32,1609.07 1771.41,1609.07 1873.72,1506.76 1873.72,1346.89 1959.85,1260.76 1959.85,1140.98 2083.3,1017.54 2083.3,918.98 2141.3,860.98 2141.3,700.31 2154.21,687.4 P2.37@2249.21,687.4
PC11: P2.38 U4.79 | length 1486.3
  Top w6.5: U4.79@1598.96,1730.78 1661.23,1730.78 1716.32,1675.69 v1(1716.32,1656.29)
  Bottom w6.5: v1(1716.32,1656.29) 1747.8,1624.81 1779.28,1624.81 1889.46,1514.63 1889.46,1353.65 1976.03,1267.08 1976.03,1144.08 2097.21,1022.9 2097.21,926.73 2157.04,866.9 2157.04,747.67 2169.21,735.5 2301.12,735.5 P2.38@2349.21,687.4
PC12: P2.35 U4.80 U7.32 | length 2995.8
  Top w6.5: v1(848.72,1011.73) 893.06,1011.73 994.09,910.69 U7.32@994.09,876.17 ; v1(1047.24,1767.72) 1054.42,1774.9 1220.51,1774.9 1236.25,1790.64 1518.75,1790.64 1558.92,1750.47 U4.80@1598.96,1750.47 1669.36,1750.47 v1(1747.8,1672.03)
  Bottom w6.5: v1(848.72,1011.73) 881.45,1011.73 889.97,1020.25 889.97,1172.61 1061.21,1343.85 1061.21,1601.06 1039.37,1622.9 1039.37,1759.84 v1(1047.24,1767.72) ; v1(1747.8,1672.03) 1779.28,1640.55 1787.15,1640.55 1905.2,1522.5 1905.2,1360.41 1990.18,1275.43 1990.18,1147.93 2115.21,1022.9 2115.21,933.13 2172.78,875.56 2172.78,791.33 2176.71,787.4 P2.35@2249.21,787.4
PC13: P2.12 U4.7 | length 1175
  Top w6.5: v1(1401.52,2167.84) 1404.07,2170.39 U4.7@1404.07,2220.94
  Bottom w6.5: v1(1401.52,2167.84) 1401.52,2204.02 1458.4,2260.9 1981.54,2260.9 2010.98,2231.19 2204.26,2037.91 2298.7,2037.91 P2.12@2349.21,1987.4
PC14: P2.9 SB16.2 | length 986.5
  Bottom w6.5: SB16.2@1490.83,2496.9 1530.21,2496.9 1537.21,2489.9 1537.21,2454.68 1572.21,2419.68 1928.81,2419.68 2101.95,2246.54 2101.95,2181.84 2196.39,2087.4 P2.9@2249.21,2087.4
PC14-OSC32_IN: R22.1 SB16.1 U4.8 | length 354.3
  Top w6.5: U4.8@1384.39,2220.94 1384.39,2257.64 1439.21,2312.46 1439.21,2443.29 v1(1440.87,2443.29) 1440.87,2455.29 1446.21,2460.63 R22.1@1473.94,2460.63
  Bottom w6.5: v1(1440.87,2443.29) 1440.87,2496.9 SB16.1@1447.53,2496.9
PC15: P2.10 SB15.2 | length 1110.9
  Bottom w6.5: SB15.2@1490.83,2552.9 1495.16,2553.38 1495.64,2552.9 1531.73,2552.9 1552.73,2531.9 1552.73,2461.9 1579.21,2435.42 1936.68,2435.42 2117.69,2254.41 2117.69,2222.93 2204.26,2136.36 2300.26,2136.36 P2.10@2349.21,2087.4
PC15-OSC32_OUT: R21.1 SB15.1 U4.9 | length 511.3
  Top w6.5: U4.9@1364.7,2220.94 1364.7,2261.89 1415.96,2313.15 1415.96,2501.25 1446.21,2531.5 R21.1@1473.94,2531.5 1473.94,2561.34 1466.07,2569.21 1454.92,2569.21 1433,2591.13 v1(1433,2592.82)
  Bottom w6.5: v1(1433,2592.82) 1433,2552.9 SB15.1@1447.53,2552.9
PD0: P2.36 U4.81 | length 1404.6
  Top w6.5: U4.81@1598.96,1770.15 1669.1,1770.15 1722.1,1717.16 1742.02,1717.16 v1(1787.15,1672.03)
  Bottom w6.5: v1(1787.15,1672.03) 1845.81,1613.37 1845.81,1605.5 1920.94,1530.37 1920.94,1367.17 2007.51,1280.6 2007.51,1148.6 2133.21,1022.9 2133.21,940.34 2187.66,885.89 2187.66,849.41 2199.21,837.86 2298.75,837.86 P2.36@2349.21,787.4
PD1: P2.33 U4.82 | length 1259.2
  Top w6.5: U4.82@1598.96,1789.84 1669.1,1789.84 1724.07,1734.87 1763.66,1734.87 v1(1826.5,1672.03)
  Bottom w6.5: v1(1826.5,1672.03) 1861.71,1636.82 1861.71,1613.21 1936.68,1538.24 1936.68,1373.93 2023.25,1287.36 2023.25,1150.86 2148.9,1025.21 2148.9,948.26 2172.78,924.38 2212.24,924.38 P2.33@2249.21,887.4
PD2: P2.34 U4.83 | length 1372.5
  Top w6.5: U4.83@1598.96,1809.52 1669.1,1809.52 1722.11,1756.52 1771.41,1756.52 1832.29,1695.64 v1(1850.11,1695.64)
  Bottom w6.5: v1(1850.11,1695.64) 1877.13,1668.62 1877.13,1621.4 1952.42,1546.11 1952.42,1380.69 2038.99,1294.12 2038.99,1159.12 2163.21,1034.9 2163.21,972.29 2196.49,939.01 2297.6,939.01 P2.34@2349.21,887.4
PD3: P2.31 U4.84 | length 1243.9
  Top w6.5: U4.84@1598.96,1829.21 1669.1,1829.21 1724.08,1774.23 1779.28,1774.23 1826.39,1727.12 1865.85,1727.12 v1(1873.72,1719.25)
  Bottom w6.5: v1(1873.72,1719.25) 1897.05,1695.92 1897.05,1625.09 1968.16,1553.98 1968.16,1387.45 2054.76,1300.85 2054.76,1161.35 2178.63,1037.48 2178.63,996.23 2187.46,987.4 P2.31@2249.21,987.4
PD4: P2.32 R43.1 U4.85 U7.1 | length 3345
  Top w6.5: v1(939.05,866.13) 940.05,866.13 950.68,855.5 U7.1@970.47,855.5 ; v1(1149.68,1797.95) 1220.51,1797.95 1236.25,1813.69 1535.31,1813.69 1543.18,1821.56 1543.18,1841.02 1551.05,1848.89 U4.85@1598.96,1848.89 1669.1,1848.89 1729.99,1788.01 1787.15,1788.01 1824.43,1750.73 v1(1873.72,1750.73) ; v1(1181.16,977.9) 1226.97,977.9 1239.86,965.01 R43.1@1239.86,963.73 1239.21,963.08 1239.21,938.9 1245.21,932.9 1293.21,932.9 1299.21,938.9 1341.21,938.9 v1(1353.21,950.9)
  Bottom w6.5: v1@939.34,865.84 1077.24,865.84 1177.89,966.48 1177.89,974.62 v1(1181.16,977.9) ; v1(1149.68,1797.95) 1133.94,1782.21 1133.94,1467.41 1173.29,1428.06 1173.29,1357.23 1165.42,1349.36 1165.42,1238.9 1203.21,1201.11 1203.21,1148.9 1299.21,1052.9 1329.21,1052.9 1353.21,1028.9 v1(1353.21,950.9) ; v1(1873.72,1750.73) 1906.71,1750.73 1920.94,1736.5 1920.94,1624.81 1983.9,1561.85 1983.9,1394.21 2070.47,1307.64 2070.47,1169.64 2197.68,1042.43 2294.19,1042.43 P2.32@2349.21,987.4
PD5: P2.29 R50.1 U4.86 | length 1875.1
  Top w6.5: U4.86@1598.96,1868.58 1669.1,1868.58 1731.96,1805.72 1810.76,1805.72 1834.27,1782.21 v1(1834.37,1774.34) ; R50.1@1743.21,896.9 1773.21,926.9 2153.21,926.9 2188.21,961.9 2188.21,1073.4 2202.21,1087.4 P2.29@2249.21,1087.4
  Bottom w6.5: v1(1834.37,1774.34) 1906.71,1774.34 1936.68,1744.37 1936.68,1632.68 1999.64,1569.72 1999.64,1400.97 2086.21,1314.4 2086.21,1173.97 2172.78,1087.4 P2.29@2249.21,1087.4
PD6: P2.30 U4.87 | length 1327.2
  Top w6.5: U4.87@1598.96,1888.26 1669.1,1888.26 1735.81,1821.56 1834.37,1821.56 v1(1850.11,1805.82)
  Bottom w6.5: v1(1850.11,1805.82) 1865.85,1790.08 1922.42,1790.08 1952.42,1760.08 1952.42,1648.42 2015.38,1585.46 2015.38,1407.73 2101.95,1321.16 2101.95,1191.96 2157.04,1136.87 2299.75,1136.87 P2.30@2349.21,1087.4
PD7: P2.27 U4.88 | length 1180.5
  Top w6.5: U4.88@1598.96,1907.95 1669.1,1907.95 1739.75,1837.3 1857.98,1837.3 v1(1881.59,1813.69)
  Bottom w6.5: v1(1881.59,1813.69) 1923.16,1813.69 1968.16,1768.69 1968.16,1664.16 2031.12,1601.2 2031.12,1414.49 2117.69,1327.92 2117.69,1223.44 2153.73,1187.4 P2.27@2249.21,1187.4
PD8: P1.40 U4.55 | length 1477
  Top w6.5: v1(942.21,1439.9) 945.21,1442.9 1025.27,1442.9 1128.48,1546.11 U4.55@1128.48,1594.96
  Bottom w6.5: P1.40@349.21,587.4 411.21,587.4 472.96,649.15 472.96,1015.65 631.21,1173.9 715.21,1173.9 907.21,1365.9 907.21,1421.9 928.21,1442.9 942.21,1442.9 v1(942.21,1439.9)
PD9: P1.41 U4.56 | length 1639.9
  Top w6.5: v1(977.21,1418.9) 984.21,1411.9 1015.47,1411.9 1148.17,1544.59 U4.56@1148.17,1594.96
  Bottom w6.5: P1.41@249.21,487.4 297.21,535.4 387.21,535.4 486.96,635.15 486.96,1005.65 641.21,1159.9 727.21,1159.9 921.21,1353.9 921.21,1404.9 931.71,1415.4 972.64,1415.4 976.14,1418.9 v1(977.21,1418.9)
PD10: P1.42 U4.57 | length 1572.8
  Top w6.5: v1(949.21,1390.9) 1020.51,1390.9 1167.85,1538.24 U4.57@1167.85,1594.96
  Bottom w6.5: P1.42@349.21,487.4 403.21,487.4 438.21,522.4 438.21,550.15 501.96,613.9 501.96,999.65 648.21,1145.9 738.21,1145.9 949.21,1356.9 v1(949.21,1390.9)
PD11: P1.43 U4.58 | length 1920.8
  Top w6.5: P1.43@249.21,387.4 300.71,438.9 394.21,438.9 409.21,453.9 409.21,789.9 438.21,818.9 531.21,818.9 578.21,865.9 578.21,991.9 606.21,1019.9 699.2,1019.9 788.71,1109.41 1063.36,1109.41 1078.85,1124.9 1078.85,1420.19 1187.54,1528.87 U4.58@1187.54,1594.96
PD12: P1.44 R40.2 U4.59 | length 1896.5
  Top w6.5: P1.44@349.21,387.4 408.93,387.4 424.21,402.69 424.21,781.9 445.21,802.9 536.21,802.9 592.21,858.9 592.21,977.9 620.21,1005.9 727.58,1005.9 814.61,1092.93 1069.62,1092.93 1092.01,1115.32 1092.01,1338.91 1094.59,1341.49 ; R40.2@1127.55,1341.49 1094.59,1341.49 ; U4.59@1207.22,1594.96 1207.22,1522.5 1094.59,1409.87 1094.59,1341.49
PD13: P1.45 R36.2 U4.60 | length 2100.3
  Top w6.5: P1.45@249.21,287.4 295.94,334.13 399.21,334.13 439.6,374.51 439.6,769.28 459.21,788.9 543.21,788.9 606.21,851.9 606.21,966.34 627.21,987.34 v1(819.14,987.34) ; v1(1118.2,1396.58) 1118.2,1410.2 1196.9,1488.9 1226.91,1488.9 ; U4.60@1226.91,1594.96 1226.91,1488.9 ; R36.2@1284.95,1483.15 1283.47,1483.15 1282.12,1484.5 1277.8,1484.5 1273.41,1488.9 1226.91,1488.9
  Bottom w6.5: v1(819.14,987.34) 968.67,987.34 985.97,1004.64 985.97,1193.91 1118.2,1326.14 v1(1118.2,1396.58)
PD14: P1.46 R41.2 U4.61 | length 2702.5
  Top w6.5: v1(1173.23,1657.48) 1236.25,1657.48 1246.59,1645.95 U4.61@1246.59,1594.96 ; v1(1413.21,1112.9) R41.2@1455.21,1160.9
  Bottom w6.5: P1.46@349.21,287.4 976.54,287.4 1000.65,263.3 1157.55,263.3 1212.64,318.39 1212.64,441.32 1414.21,642.89 1414.21,1112.9 1414.21,1117.9 v1(1413.21,1112.9) 1403.75,1118.9 1401.52,1121.13 1276.71,1121.13 1236.25,1161.59 1236.25,1208.66 1204.72,1240.19 1204.72,1444.88 1165.35,1484.25 1165.35,1649.61 v1(1173.23,1657.48)
PD15: P1.47 R42.2 U4.62 | length 3032.8
  Top w6.5: v1(1157.48,1688.98) 1242.67,1688.98 1266.28,1664.16 U4.62@1266.28,1594.96 ; v1(1389.21,1076.9) 1402.21,1089.9 1488.83,1089.9 1499.21,1079.52 R42.2@1498.21,1053.9
  Bottom w6.5: P1.47@249.21,187.4 299.72,237.91 299.72,326.26 307.59,334.13 398.91,334.13 418.58,314.45 972.61,314.45 1008.02,279.04 1149.68,279.04 1192.86,322.21 1192.86,458.34 1389.21,654.7 v1(1389.21,1076.9) 1301.5,1076.9 1220.51,1157.89 1220.51,1204.72 1188.98,1236.26 1188.98,1437.01 1149.61,1476.38 1149.61,1681.1 v1(1157.48,1688.98)
PE0: P2.17 U4.97 U5.12 | length 2468.8
  Top w6.5: v1(1179.21,2078.9) 1179.21,2075.11 1209.21,2045.11 1469.21,2045.11 1509.21,2085.11 U4.97@1598.96,2085.11 1653.36,2085.11 1667.06,2098.81 1842.24,2098.81 1856.18,2112.75 v1(1857.98,2112.75) ; v2(1302.09,1162.71) 1302.09,1191.42 U5.12@1304.55,1193.88
  Bottom w6.5: v1(1179.21,2078.9) 1199.21,2058.9 1199.21,1988.9 1229.21,1958.9 1229.21,1897.64 1259.37,1867.48 1259.37,1503.46 1291.34,1471.5 1291.34,1375.47 1386.5,1280.32 1386.5,1233.18 1377.22,1223.9 1335.46,1223.9 1302.09,1190.53 v2(1302.09,1162.71) ; v1(1857.98,2112.75) 1907.01,2112.75 1928.81,2090.95 1977.16,2090.95 2054.73,2013.38 2054.73,1978.96 2141.3,1892.39 2141.3,1782.21 2196.39,1727.12 2209.5,1727.12 P2.17@2249.21,1687.4
PE1: P2.18 U4.98 U5.11 | length 2650.2
  Top w6.5: v1(1220.51,2081.27) 1236.25,2065.53 1465.31,2065.53 1504.58,2104.8 U4.98@1598.96,2104.8 1645.49,2104.8 1655.59,2114.9 1818.63,2114.9 1847.96,2144.23 v1(1873.72,2144.23) ; U5.11@1284.86,1193.88 1279.86,1188.88 1279.86,1148.75 1298.89,1129.72 1372.11,1129.72 1384.39,1142 v2(1384.39,1178.79)
  Bottom w6.5: v1(1220.51,2081.27) 1220.51,2008.9 1249.21,1980.2 1249.21,1909.45 1271.65,1887.01 1271.65,1507.24 1306.46,1472.44 1306.46,1380.63 1418.19,1268.9 1418.19,1188.9 1408.09,1178.79 v2(1384.39,1178.79) ; v1(1873.72,2144.23) 1946.38,2144.23 2070.47,2020.14 2070.47,1986.83 2157.04,1900.26 2157.04,1797.95 2204.26,1750.73 2212.13,1750.73 2227.87,1734.99 2298.7,1734.99 2346.29,1687.4 P2.18@2349.21,1687.4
